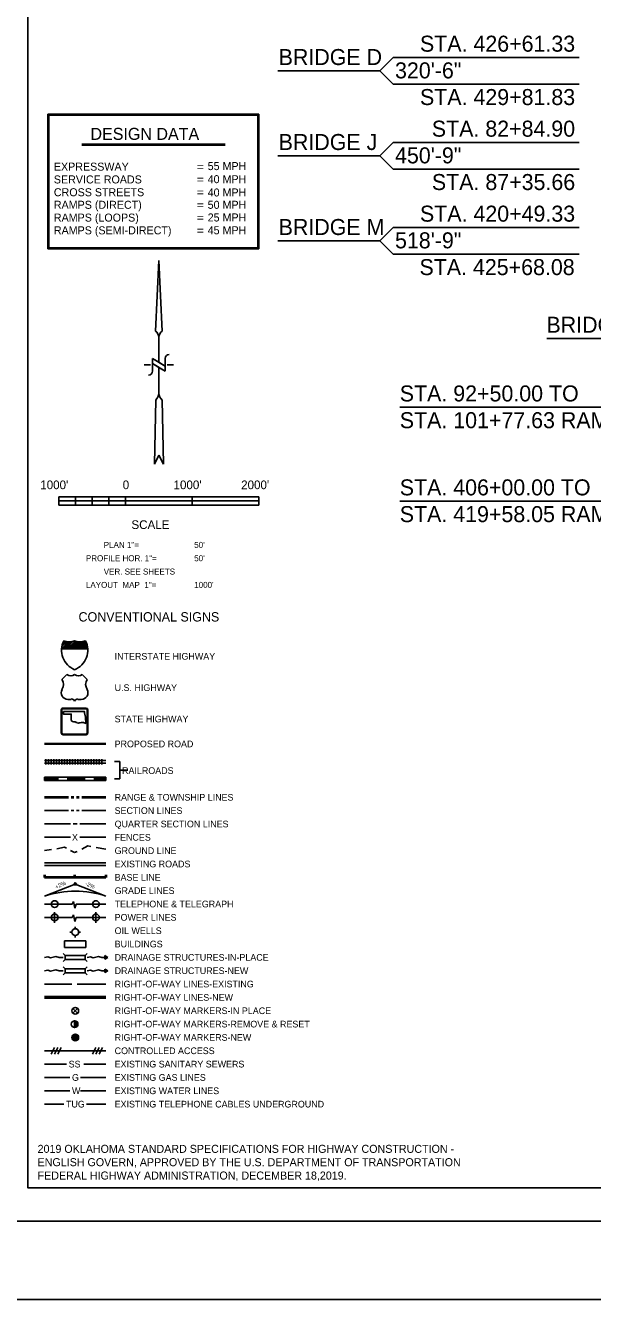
# Model space of a CAD drawing. Extents: x 2121385 to 2181200, y 132498 to 161273.
# Drawn here: x 2134915 to 2143424, y 132498 to 151597 of the extents above; entities that cross this region are included whole.
import ezdxf

# ---------------------------------------------------------------- set-up
doc = ezdxf.new("R2010")
doc.units = 0
for name, color, linetype in [('4', 7, 'Continuous'), ('5', 7, 'Continuous'), ('SHT_North_Arrow', 7, 'Continuous'), ('SHT_Plot_Shape_Full', 7, 'Continuous'), ('SHT_Plot_Shape_Half', 7, 'Continuous'), ('SHT_Scale', 7, 'Continuous'), ('SHT_Sheet_Border', 7, 'Continuous'), ('SHT_Title_Sheet_Design_Traffic', 7, 'Continuous'), ('SHT_Title_Sheet_Misc', 7, 'Continuous')]:
    doc.layers.add(name, color=color, linetype=linetype)

msp = doc.modelspace()

# ---------------------------------------------------------------- linework, layer by layer
at = {"layer": '4'}
for p, q in [((2140433, 151119), (2140233, 150919)), ((2140433, 151119), (2143224, 151119)), ((2138703, 150919), (2140233, 150919)), ((2140433, 150718), (2140233, 150919)), ((2140433, 150718), (2143224, 150718)), ((2140433, 149844), (2140233, 149644)), ((2140433, 149844), (2143224, 149844)), ((2138703, 149644), (2140233, 149644)), ((2140433, 149444), (2140233, 149644)), ((2140433, 149444), (2143224, 149444)), ((2140433, 148570), (2140233, 148370)), ((2140433, 148570), (2143224, 148570)), ((2138703, 148370), (2140233, 148370)), ((2140433, 148170), (2140233, 148370)), ((2140433, 148170), (2143224, 148170))]:
    msp.add_line(p, q, dxfattribs=at)
at = {"layer": '5'}
for points in [[(2142737, 146905), (2144226, 146905), (2150332, 143606)], [(2140533, 145876), (2144226, 145876), (2150201, 143459)], [(2140533, 144467), (2144226, 144467), (2149865, 143332)]]:
    msp.add_lwpolyline(points, dxfattribs=at)
at = {"layer": 'SHT_North_Arrow'}
for p, q in [((2136868, 147017), (2136917, 148075)), ((2136917, 148075), (2136868, 147017)), ((2136917, 148075), (2136965, 147017)), ((2136965, 147017), (2136917, 148075)), ((2136917, 146549), (2136917, 146923)), ((2136792, 146511), (2136696, 146511)), ((2137012, 146491), (2136821, 146607)), ((2136821, 146607), (2137012, 146491)), ((2136821, 146607), (2136821, 146415)), ((2136917, 146549), (2136821, 146607)), ((2136821, 146607), (2136821, 146530)), ((2137012, 146415), (2136821, 146530)), ((2137012, 146491), (2136917, 146549)), ((2137012, 146607), (2137012, 146415)), ((2137012, 146415), (2137012, 146491)), ((2137137, 146511), (2137041, 146511)), ((2136917, 146079), (2136917, 146472)), ((2136849, 145023), (2136869, 145983)), ((2136869, 145983), (2136849, 145023)), ((2136984, 145023), (2136965, 145983)), ((2136984, 145023), (2136965, 145983)), ((2136849, 145023), (2136917, 145158)), ((2136849, 145023), (2136917, 145158)), ((2136917, 145158), (2136984, 145023)), ((2136917, 145158), (2136984, 145023))]:
    msp.add_line(p, q, dxfattribs=at)
for points in [[(2136821, 146530), (2136917, 146472), (2137012, 146415)], [(2136917, 146079), (2136917, 146079), (2136916, 146079)]]:
    msp.add_lwpolyline(points, dxfattribs=at)
for centre, radius, start, end in [((2136801, 146923), 115, 0, 54.3802), ((2136801, 146923), 115, 0, 54.3802), ((2137032, 146923), 115, 125.6198, 180), ((2137032, 146923), 115, 125.6198, 180), ((2137070, 146607), 57.6, 90, 180), ((2136763, 146415), 57.6, 270, 0), ((2136750, 146102), 169, 314.9567, 352.4189), ((2136750, 146102), 169, 314.9567, 352.059), ((2137084, 146102), 169, 187.5811, 225.0433), ((2137084, 146102), 169, 187.941, 225.0433)]:
    msp.add_arc(centre, radius, start, end, dxfattribs=at)
at = {"layer": 'SHT_Plot_Shape_Full'}
msp.add_lwpolyline([(2131361, 156498), (2167361, 156498), (2167361, 132498), (2131361, 132498)], close=True, dxfattribs=at)
at = {"layer": 'SHT_Plot_Shape_Half'}
msp.add_lwpolyline([(2132999, 155673), (2166999, 155673), (2166999, 133673), (2132999, 133673)], close=True, dxfattribs=at)
at = {"layer": 'SHT_Scale'}
for p, q in [((2135417, 144532), (2135417, 144407)), ((2135417, 144532), (2138417, 144532)), ((2135417, 144532), (2135417, 144469)), ((2135667, 144532), (2135417, 144532)), ((2135417, 144469), (2138417, 144469)), ((2135417, 144469), (2135667, 144469)), ((2135417, 144407), (2138417, 144407)), ((2135667, 144532), (2135667, 144469)), ((2135667, 144469), (2135667, 144532)), ((2135667, 144469), (2135667, 144407)), ((2135917, 144469), (2135667, 144469)), ((2135667, 144469), (2135667, 144407)), ((2135667, 144407), (2135917, 144407)), ((2135917, 144532), (2135917, 144407)), ((2136167, 144532), (2135917, 144532)), ((2135917, 144532), (2135917, 144469)), ((2135917, 144407), (2135917, 144469)), ((2135917, 144469), (2136167, 144469)), ((2136167, 144532), (2136167, 144407)), ((2136167, 144469), (2136167, 144532)), ((2136417, 144469), (2136167, 144469)), ((2136167, 144469), (2136167, 144407)), ((2136167, 144407), (2136417, 144407)), ((2136417, 144407), (2136417, 144532)), ((2137417, 144532), (2136417, 144532)), ((2136417, 144532), (2136417, 144469)), ((2136417, 144407), (2136417, 144469)), ((2136417, 144469), (2137417, 144469)), ((2137417, 144532), (2137417, 144407)), ((2137417, 144469), (2137417, 144532)), ((2138417, 144469), (2137417, 144469)), ((2137417, 144469), (2137417, 144407)), ((2137417, 144407), (2138417, 144407)), ((2138417, 144532), (2138417, 144407)), ((2138417, 144407), (2138417, 144469))]:
    msp.add_line(p, q, dxfattribs=at)
at = {"layer": 'SHT_Sheet_Border'}
msp.add_lwpolyline([(2166449, 134173), (2134949, 134173), (2134949, 155173), (2166449, 155173)], close=True, dxfattribs=at)
at = {"layer": 'SHT_Title_Sheet_Design_Traffic'}
for p, q in [((2135759, 149816), (2137909, 149816)), ((2135759, 149804), (2137909, 149804))]:
    msp.add_line(p, q, dxfattribs=at)
for points in [[(2135253, 150266), (2138415, 150266), (2138415, 148251), (2135253, 148251)], [(2135265, 150254), (2138403, 150254), (2138403, 148263), (2135265, 148263)]]:
    msp.add_lwpolyline(points, close=True, dxfattribs=at)
at = {"layer": 'SHT_Title_Sheet_Misc'}
for p, q in [((2135459, 142260), (2135556, 142357)), ((2135462, 142287), (2135535, 142360)), ((2135469, 142316), (2135517, 142364)), ((2135473, 142252), (2135578, 142356)), ((2135481, 142351), (2135499, 142370)), ((2135496, 142252), (2135603, 142358)), ((2135519, 142252), (2135632, 142365)), ((2135542, 142252), (2135660, 142369)), ((2135565, 142252), (2135677, 142364)), ((2135588, 142252), (2135696, 142360)), ((2135611, 142252), (2135716, 142357)), ((2135634, 142252), (2135739, 142356)), ((2135657, 142252), (2135764, 142359)), ((2135680, 142252), (2135793, 142365)), ((2135703, 142252), (2135818, 142367)), ((2135726, 142252), (2135825, 142351)), ((2135749, 142252), (2135832, 142334)), ((2135772, 142252), (2135837, 142317)), ((2135795, 142252), (2135842, 142298)), ((2135458, 142252), (2135848, 142252)), ((2135818, 142252), (2135845, 142279)), ((2135841, 142252), (2135848, 142259)), ((2135463, 141795), (2135538, 141870)), ((2135843, 141795), (2135768, 141870)), ((2135603, 141495), (2135553, 141495)), ((2135703, 141495), (2135753, 141495)), ((2135203, 140833), (2136123, 140833)), ((2135203, 140821), (2136123, 140821)), ((2135203, 140577), (2136123, 140577)), ((2135223, 140517), (2135223, 140597)), ((2135263, 140517), (2135263, 140597)), ((2135303, 140517), (2135303, 140597)), ((2135343, 140517), (2135343, 140597)), ((2135383, 140517), (2135383, 140597)), ((2135423, 140517), (2135423, 140597)), ((2135463, 140517), (2135463, 140597)), ((2135503, 140517), (2135503, 140597)), ((2135543, 140517), (2135543, 140597)), ((2135583, 140517), (2135583, 140597)), ((2135623, 140517), (2135623, 140597)), ((2135663, 140517), (2135663, 140597)), ((2135703, 140517), (2135703, 140597)), ((2135743, 140517), (2135743, 140597)), ((2135783, 140517), (2135783, 140597)), ((2135823, 140517), (2135823, 140597)), ((2135863, 140517), (2135863, 140597)), ((2135903, 140517), (2135903, 140597)), ((2135943, 140517), (2135943, 140597)), ((2135983, 140517), (2135983, 140597)), ((2136023, 140517), (2136023, 140597)), ((2136063, 140517), (2136063, 140597)), ((2135203, 140537), (2136123, 140537)), ((2136253, 140562), (2136333, 140562)), ((2136333, 140302), (2136333, 140562)), ((2136333, 140432), (2136453, 140432)), ((2135203, 140331), (2135403, 140331)), ((2135203, 140277), (2135203, 140327)), ((2135203, 140327), (2136123, 140327)), ((2135203, 140319), (2135403, 140319)), ((2135203, 140307), (2135403, 140307)), ((2135203, 140295), (2135403, 140295)), ((2135203, 140283), (2135403, 140283)), ((2136123, 140277), (2135203, 140277)), ((2135403, 140277), (2135403, 140327)), ((2135553, 140331), (2135803, 140331)), ((2135553, 140277), (2135553, 140327)), ((2135553, 140319), (2135803, 140319)), ((2135553, 140307), (2135803, 140307)), ((2135553, 140295), (2135803, 140295)), ((2135553, 140283), (2135803, 140283)), ((2135803, 140277), (2135803, 140327)), ((2135953, 140331), (2136123, 140331)), ((2135953, 140277), (2135953, 140327)), ((2135953, 140319), (2136123, 140319)), ((2135953, 140307), (2136123, 140307)), ((2135953, 140295), (2136123, 140295)), ((2135953, 140283), (2136123, 140283)), ((2136123, 140327), (2136123, 140277)), ((2136253, 140302), (2136333, 140302)), ((2135203, 140033), (2135563, 140033)), ((2135203, 140021), (2135563, 140021)), ((2135603, 140033), (2135643, 140033)), ((2135603, 140021), (2135643, 140021)), ((2135683, 140033), (2135723, 140033)), ((2135683, 140021), (2135723, 140021)), ((2135763, 140033), (2136123, 140033)), ((2135763, 140021), (2136123, 140021)), ((2135203, 139827), (2135563, 139827)), ((2135603, 139827), (2135643, 139827)), ((2135683, 139827), (2135723, 139827)), ((2135763, 139827), (2136123, 139827)), ((2135203, 139627), (2135593, 139627)), ((2135633, 139627), (2135693, 139627)), ((2135733, 139627), (2136123, 139627)), ((2135203, 139427), (2135593, 139427)), ((2135733, 139427), (2136123, 139427)), ((2135203, 139227), (2135307, 139244)), ((2135387, 139255), (2135503, 139277)), ((2135503, 139277), (2135529, 139263)), ((2135593, 139229), (2135653, 139197)), ((2135762, 139251), (2135853, 139297)), ((2135853, 139297), (2135898, 139289)), ((2135978, 139274), (2136123, 139247)), ((2135203, 139047), (2136123, 139047)), ((2135653, 139197), (2135689, 139215)), ((2135197, 138827), (2135197, 138867)), ((2135203, 139007), (2136123, 139007)), ((2135209, 138827), (2135209, 138867)), ((2135647, 138827), (2135647, 138867)), ((2135659, 138827), (2135659, 138867)), ((2136117, 138827), (2136117, 138867)), ((2136129, 138827), (2136129, 138867)), ((2135203, 138833), (2136123, 138833)), ((2135203, 138821), (2136123, 138821)), ((2135203, 138547), (2135663, 138727)), ((2135642, 138715), (2135663, 138752)), ((2135685, 138715), (2135642, 138715)), ((2135663, 138752), (2135685, 138715)), ((2135663, 138727), (2136123, 138547)), ((2135617, 138427), (2135638, 138467)), ((2135638, 138467), (2135658, 138367)), ((2135203, 138427), (2135617, 138427)), ((2135353, 138147), (2135353, 138307)), ((2135658, 138367), (2135677, 138427)), ((2135677, 138427), (2136123, 138427)), ((2135973, 138147), (2135973, 138307)), ((2135203, 138227), (2135617, 138227)), ((2135617, 138227), (2135638, 138267)), ((2135638, 138267), (2135658, 138167)), ((2135658, 138167), (2135677, 138227)), ((2135663, 138057), (2135663, 138087)), ((2135677, 138227), (2136123, 138227)), ((2135583, 138007), (2135613, 138007)), ((2135663, 137927), (2135663, 137957)), ((2135713, 138007), (2135743, 138007)), ((2135503, 137777), (2135503, 137877)), ((2135503, 137877), (2135823, 137877)), ((2135823, 137777), (2135503, 137777)), ((2135823, 137877), (2135823, 137777)), ((2135203, 137627), (2135253, 137637)), ((2135253, 137637), (2135293, 137622)), ((2135293, 137622), (2135373, 137642)), ((2135373, 137642), (2135423, 137627)), ((2135423, 137627), (2135483, 137627)), ((2135513, 137657), (2135483, 137687)), ((2135513, 137597), (2135483, 137567)), ((2135513, 137597), (2135513, 137657)), ((2135513, 137657), (2135813, 137657)), ((2135813, 137597), (2135513, 137597)), ((2135813, 137657), (2135843, 137687)), ((2135813, 137657), (2135813, 137597)), ((2135813, 137597), (2135843, 137567)), ((2135843, 137627), (2135893, 137637)), ((2135893, 137637), (2135933, 137622)), ((2135933, 137622), (2136013, 137642)), ((2136013, 137642), (2136063, 137627)), ((2136063, 137627), (2136123, 137627)), ((2136108, 137653), (2136153, 137627)), ((2136108, 137601), (2136108, 137653)), ((2136153, 137627), (2136108, 137601)), ((2135203, 137427), (2135253, 137437)), ((2135253, 137437), (2135293, 137422)), ((2135293, 137422), (2135373, 137442)), ((2135373, 137442), (2135423, 137427)), ((2135423, 137427), (2135483, 137427)), ((2135513, 137457), (2135483, 137487)), ((2135513, 137397), (2135483, 137367)), ((2135513, 137397), (2135513, 137457)), ((2135513, 137457), (2135813, 137457)), ((2135813, 137397), (2135513, 137397)), ((2135813, 137457), (2135843, 137487)), ((2135813, 137457), (2135813, 137397)), ((2135813, 137397), (2135843, 137367)), ((2135843, 137427), (2135893, 137437)), ((2135893, 137437), (2135933, 137422)), ((2135933, 137422), (2136013, 137442)), ((2136013, 137442), (2136063, 137427)), ((2136063, 137427), (2136123, 137427)), ((2136108, 137453), (2136153, 137427)), ((2136108, 137401), (2136108, 137453)), ((2136153, 137427), (2136108, 137401)), ((2135203, 137227), (2135613, 137227)), ((2135689, 137227), (2136123, 137227)), ((2135203, 137039), (2136123, 137039)), ((2135203, 137027), (2136123, 137027)), ((2135203, 137015), (2136123, 137015)), ((2135698, 136862), (2135628, 136792)), ((2135628, 136862), (2135698, 136792)), ((2135653, 136577), (2135653, 136677)), ((2135656, 136676), (2135655, 136676)), ((2135655, 136676), (2135655, 136578)), ((2135656, 136579), (2135656, 136676)), ((2135657, 136672), (2135658, 136583)), ((2135658, 136583), (2135661, 136584)), ((2135661, 136584), (2135661, 136671)), ((2135661, 136671), (2135664, 136670)), ((2135663, 136577), (2135663, 136677)), ((2135664, 136670), (2135664, 136584)), ((2135664, 136584), (2135668, 136586)), ((2135668, 136586), (2135668, 136669)), ((2135668, 136669), (2135671, 136667)), ((2135671, 136667), (2135671, 136587)), ((2135671, 136587), (2135674, 136589)), ((2135674, 136589), (2135675, 136666)), ((2135675, 136666), (2135679, 136663)), ((2135679, 136663), (2135679, 136592)), ((2135679, 136592), (2135682, 136595)), ((2135682, 136595), (2135682, 136659)), ((2135682, 136659), (2135686, 136656)), ((2135686, 136656), (2135686, 136599)), ((2135686, 136599), (2135689, 136602)), ((2135689, 136602), (2135688, 136652)), ((2135688, 136652), (2135692, 136647)), ((2135692, 136647), (2135692, 136608)), ((2135692, 136608), (2135695, 136615)), ((2135695, 136615), (2135695, 136641)), ((2135203, 136227), (2136123, 136227)), ((2135303, 136177), (2135353, 136277)), ((2135353, 136177), (2135403, 136277)), ((2135403, 136177), (2135453, 136277)), ((2135923, 136177), (2135973, 136277)), ((2135973, 136177), (2136023, 136277)), ((2136023, 136177), (2136073, 136277)), ((2135203, 136027), (2135533, 136027)), ((2135793, 136027), (2136123, 136027)), ((2135203, 135827), (2135583, 135827)), ((2135743, 135827), (2136123, 135827)), ((2135203, 135627), (2135583, 135627)), ((2135743, 135627), (2136123, 135627)), ((2135203, 135427), (2135493, 135427)), ((2135833, 135427), (2136123, 135427))]:
    msp.add_line(p, q, dxfattribs=at)
for points in [[(2135452, 140992), (2135452, 141340)], [(2135463, 140992), (2135463, 141340)], [(2135480, 141364), (2135826, 141364)], [(2135480, 141354), (2135826, 141354)], [(2135842, 141339), (2135842, 140991)], [(2135853, 141339), (2135853, 140991)], [(2135602, 141178), (2135603, 141274), (2135485, 141275), (2135488, 141313), (2135801, 141313), (2135801, 141292), (2135818, 141229), (2135820, 141135), (2135788, 141150), (2135771, 141146), (2135771, 141146), (2135753, 141148), (2135732, 141142), (2135720, 141145), (2135708, 141139), (2135688, 141142), (2135679, 141155), (2135671, 141147), (2135666, 141153), (2135663, 141161), (2135659, 141163), (2135658, 141159), (2135654, 141157), (2135646, 141157), (2135642, 141163), (2135637, 141158), (2135621, 141163), (2135602, 141178)], [(2135827, 140975), (2135480, 140975)], [(2135827, 140964), (2135480, 140964)]]:
    msp.add_lwpolyline(points, dxfattribs=at)
for centre, radius in [((2135353, 138427), 50), ((2135973, 138427), 50), ((2135353, 138227), 50), ((2135973, 138227), 50), ((2135663, 138007), 50), ((2135663, 136827), 50), ((2135653, 136627), 50), ((2135663, 136427), 50), ((2135663, 136427), 40), ((2135663, 136427), 30), ((2135663, 136427), 20), ((2135663, 136427), 10.5), ((2135663, 136427), 3.14)]:
    msp.add_circle(centre, radius, dxfattribs=at)
for centre, radius, start, end in [((2135773, 142232), 316, 153.4721, 176.3707), ((2135773, 142232), 316, 153.4349, 247.6594), ((2135573, 142572), 215, 247.4926, 291.8014), ((2135573, 142572), 215, 248.1986, 291.8014), ((2135733, 142572), 215, 248.1986, 292.5074), ((2135533, 142232), 316, 292.3406, 26.5651), ((2135733, 142572), 215, 248.1986, 291.8014), ((2135533, 142232), 316, 3.6293, 26.5279), ((2135363, 141720), 125, 323.1301, 36.8699), ((2135594, 141929), 83.4, 227.8156, 315), ((2135712, 141929), 83.4, 225, 312.1844), ((2135943, 141720), 125, 143.1301, 216.8699), ((2135553, 141595), 100, 150.9454, 270), ((2135753, 141595), 100, 270, 29.0546), ((2135477, 141340), 24.4, 81.4421, 180), ((2135477, 141340), 14, 78.7027, 180), ((2135603, 141445), 55.9, 26.5651, 90), ((2135703, 141445), 55.9, 90, 153.4349), ((2135826, 141338), 26.5, 3.4931, 90), ((2135826, 141338), 16.1, 4.4777, 90), ((2135480, 140992), 28, 180.0223, 270), ((2135480, 140992), 17.6, 180.0223, 270), ((2135826, 140991), 26.5, 271.6882, 0), ((2135826, 140991), 16.1, 272.1653, 0), ((2135663, 137107), 1512, 72.2842, 107.7158), ((2135653, 136627), 48.5, 273.2985, 87.3164), ((2135652, 136627), 46.8, 275.92, 85.4314), ((2135653, 136627), 44.6, 275.9956, 84.1322)]:
    msp.add_arc(centre, radius, start, end, dxfattribs=at)

# ---------------------------------------------------------------- texts
at = {"layer": '4'}
for s, p in [('STA. 426+61.33', (2140834, 151204)), ('BRIDGE D', (2138714, 151004)), ('320\'-6"', (2140460, 150804)), ('STA. 429+81.83', (2140834, 150404)), ('STA. 82+84.90', (2141012, 149930)), ('BRIDGE J', (2138714, 149730)), ('450\'-9"', (2140460, 149530)), ('STA. 87+35.66', (2141013, 149130)), ('STA. 420+49.33', (2140834, 148656)), ('BRIDGE M', (2138714, 148456)), ('518\'-9"', (2140460, 148256)), ('STA. 425+68.08', (2140827, 147855)), ('BRIDGE B', (2142732, 146991)), ('STA. 92+50.00 TO', (2140531, 145961)), ('STA. 101+77.63 RAMP A', (2140531, 145560)), ('STA. 406+00.00 TO', (2140531, 144553)), ('STA. 419+58.05 RAMP F', (2140531, 144152))]:
    msp.add_text(s, height=240, dxfattribs=at).set_placement(p)
at = {"layer": 'SHT_Scale'}
for s, height, p in [("1000'", 130, (2135137, 144646)), ('0', 130, (2136374, 144646)), ("1000'", 130, (2137137, 144646)), ("2000'", 130, (2138151, 144646)), ('SCALE', 130, (2136505, 144049)), ('          PLAN 1"=', 90, (2135755, 143766)), ("50'", 90, (2137447, 143766)), ('  PROFILE HOR. 1"=', 90, (2135755, 143566)), ("50'", 90, (2137447, 143566)), ('          VER. SEE SHEETS', 90, (2135755, 143366)), ('  LAYOUT  MAP  1"=', 90, (2135755, 143166)), ("1000'", 90, (2137447, 143166))]:
    msp.add_text(s, height=height, dxfattribs=at).set_placement(p)
at = {"layer": 'SHT_Title_Sheet_Design_Traffic'}
for s, height, p in [('DESIGN DATA', 180, (2135890, 149882)), ('EXPRESSWAY', 120, (2135341, 149421)), ('55 MPH', 120, (2137649, 149429)), ('SERVICE ROADS', 120, (2135341, 149229)), ('=', 120, (2137488, 149421)), ('=', 120, (2137498, 149421)), ('40 MPH', 120, (2137649, 149233)), ('=', 120, (2137488, 149229)), ('=', 120, (2137498, 149229)), ('CROSS STREETS', 120, (2135341, 149037)), ('RAMPS (DIRECT)', 120, (2135341, 148849)), ('=', 120, (2137488, 149037)), ('=', 120, (2137498, 149037)), ('40 MPH', 120, (2137649, 149034)), ('50 MPH', 120, (2137649, 148849)), ('RAMPS (LOOPS)', 120, (2135341, 148657)), ('=', 120, (2137488, 148845)), ('=', 120, (2137498, 148845)), ('25 MPH', 120, (2137649, 148659)), ('RAMPS (SEMI-DIRECT)', 120, (2135341, 148466)), ('=', 120, (2137488, 148657)), ('=', 120, (2137498, 148657)), ('45 MPH', 120, (2137649, 148467)), ('=', 120, (2137488, 148464)), ('=', 120, (2137498, 148464))]:
    msp.add_text(s, height=height, dxfattribs=at).set_placement(p)
at = {"layer": 'SHT_Title_Sheet_Misc'}
for s, height, p in [('CONVENTIONAL SIGNS', 140, (2135711, 142662)), ('INTERSTATE HIGHWAY', 100, (2136253, 142090)), ('U.S. HIGHWAY', 100, (2136253, 141620)), ('STATE HIGHWAY', 100, (2136253, 141151)), ('PROPOSED ROAD', 100, (2136253, 140777)), ('   RAILROADS', 100, (2136253, 140377)), ('RANGE & TOWNSHIP LINES', 100, (2136253, 139977)), ('SECTION LINES', 100, (2136253, 139777)), ('QUARTER SECTION LINES', 100, (2136253, 139577)), ('X', 100, (2135613, 139377)), ('FENCES', 100, (2136253, 139377)), ('GROUND LINE', 100, (2136253, 139177)), ('EXISTING ROADS', 100, (2136253, 138977)), ('BASE LINE', 100, (2136253, 138777)), ('GRADE LINES', 100, (2136253, 138577)), ('TELEPHONE & TELEGRAPH', 100, (2136253, 138377)), ('POWER LINES', 100, (2136253, 138177)), ('OIL WELLS', 100, (2136253, 137977)), ('BUILDINGS', 100, (2136253, 137777)), ('DRAINAGE STRUCTURES-IN-PLACE', 100, (2136253, 137577)), ('DRAINAGE STRUCTURES-NEW', 100, (2136253, 137377)), ('RIGHT-OF-WAY LINES-EXISTING', 100, (2136253, 137177)), ('RIGHT-OF-WAY LINES-NEW', 100, (2136253, 136977)), ('RIGHT-OF-WAY MARKERS-IN PLACE', 100, (2136253, 136777)), ('RIGHT-OF-WAY MARKERS-REMOVE & RESET', 100, (2136253, 136577)), ('RIGHT-OF-WAY MARKERS-NEW', 100, (2136253, 136377)), ('CONTROLLED ACCESS', 100, (2136253, 136177)), ('SS', 100, (2135563, 135977)), ('EXISTING SANITARY SEWERS', 100, (2136253, 135977)), ('G', 100, (2135613, 135777)), ('EXISTING GAS LINES', 100, (2136253, 135777)), ('W', 100, (2135613, 135577)), ('EXISTING WATER LINES', 100, (2136253, 135577)), ('TUG', 100, (2135523, 135377)), ('EXISTING TELEPHONE CABLES UNDERGROUND', 100, (2136253, 135377)), ('2019 OKLAHOMA STANDARD SPECIFICATIONS FOR HIGHWAY CONSTRUCTION -', 120, (2135097, 134697)), ('ENGLISH GOVERN, APPROVED BY THE U.S. DEPARTMENT OF TRANSPORTATION', 120, (2135097, 134497)), ('FEDERAL HIGHWAY ADMINISTRATION, DECEMBER 18,2019. ', 120, (2135097, 134297))]:
    msp.add_text(s, height=height, dxfattribs=at).set_placement(p)
for s, rotation, p in [('+2%', 25, (2135376, 138650)), ('-2%', 335, (2135807, 138712))]:
    msp.add_text(s, height=60, rotation=rotation, dxfattribs=at).set_placement(p)

doc.saveas('drawing.dxf')
